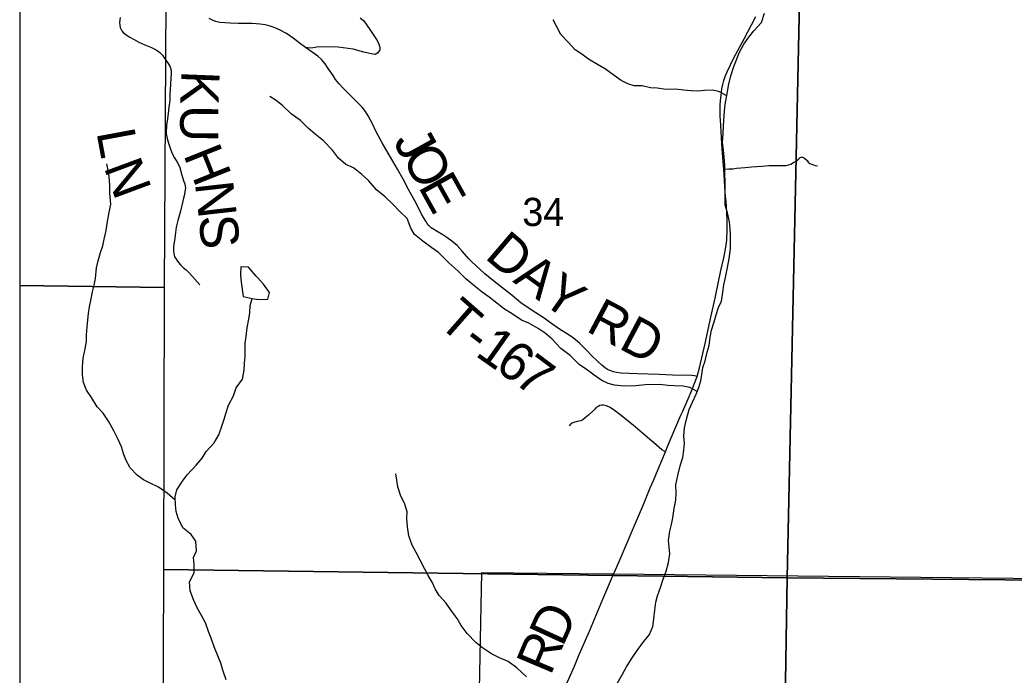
# Model space of a CAD drawing. Extents: x 0 to 191, y 0 to 55.
# Drawn here: x 184.17 to 185.647, y 51.316 to 52.289 of the extents above; entities that cross this region are included whole.
import ezdxf

# ---------------------------------------------------------------- set-up
doc = ezdxf.new("R2010")
doc.units = 0
for name, color, linetype in [('GM_X_Corporation', 7, 'Continuous'), ('GM_X_County_Road', 7, 'Continuous'), ('GM_X_County_Road_Text', 7, 'Continuous'), ('GM_X_Minor_Lake', 7, 'Continuous'), ('GM_X_Minor_River', 7, 'Continuous'), ('GM_X_Section_Text', 7, 'Continuous'), ('GM_X_Township_Road', 7, 'Continuous'), ('GM_X_Township_Road_Text', 7, 'Continuous')]:
    doc.layers.add(name, color=color, linetype=linetype)

msp = doc.modelspace()

# ---------------------------------------------------------------- linework, layer by layer
at = {"layer": 'GM_X_Corporation'}
for points in [[(187.8766, 54.1257), (187.4205, 54.1315), (187.3845, 54.1319), (186.7662, 54.1447), (186.7401, 54.1422), (185.9791, 54.1551), (185.8681, 54.1568), (185.8476, 54.1564), (184.4129, 54.1665), (184.4114, 53.9192), (184.1701, 53.923), (184.1701, 47.9197)], [(184.8319, 50.3472), (184.8438, 50.7018), (184.8438, 50.7041), (184.8504, 51.1664), (184.8504, 51.1691), (184.8564, 51.468), (185.0493, 51.466), (185.0519, 51.466), (185.737, 51.4587), (185.8223, 51.4579), (185.8471, 52.9493), (185.8472, 52.953), (185.8634, 53.9305), (185.8653, 54.0182), (185.8655, 54.0321), (185.8681, 54.1568), (185.8476, 54.1564), (184.4129, 54.1665), (184.4114, 53.9192), (184.1701, 53.923), (184.1701, 49.9388)], [(184.8319, 50.3472), (184.8438, 50.7018), (184.8438, 50.7041), (184.8504, 51.1664), (184.8504, 51.1691), (184.8564, 51.468), (185.0493, 51.466), (185.0519, 51.466), (185.737, 51.4587), (185.8223, 51.4579), (185.8471, 52.9493), (185.8472, 52.953), (185.8634, 53.9305), (185.8653, 54.0182), (185.8655, 54.0321), (185.8681, 54.1568), (185.9791, 54.1551), (186.7401, 54.1422), (186.7662, 54.1447), (187.3845, 54.1319), (187.4205, 54.1315), (187.8766, 54.1257)]]:
    msp.add_lwpolyline(points, dxfattribs=at)
for points in [[(184.1701, 52.9098), (184.1701, 51.8943), (184.385, 51.8913), (184.3885, 52.4898), (184.3932, 52.9078)], [(184.3885, 52.4898), (185.3319, 52.4794), (185.31, 51.4601), (184.3837, 51.4722), (184.385, 51.8913)], [(185.3319, 52.4794), (186.3443, 52.462), (186.336, 51.4505), (185.31, 51.4601)], [(184.1701, 51.8943), (184.1701, 50.9485), (184.3819, 50.9465), (184.3837, 51.4722), (184.385, 51.8913)], [(185.31, 51.4601), (185.2935, 50.4401), (184.3778, 50.4493), (184.3819, 50.9465), (184.3837, 51.4722)], [(186.336, 51.4505), (186.3245, 50.4222), (185.2935, 50.4401), (185.31, 51.4601)]]:
    msp.add_lwpolyline(points, close=True, dxfattribs=at)
at = {"layer": 'GM_X_County_Road'}
for points in [[(185.0533, 51.4683), (185.0619, 51.488), (185.0816, 51.5344), (185.0963, 51.5691), (185.1064, 51.5937), (185.1112, 51.6045), (185.1185, 51.6216), (185.129, 51.6472), (185.1323, 51.6551), (185.1447, 51.6844), (185.1522, 51.7018), (185.1549, 51.7079), (185.163, 51.726), (185.1684, 51.7388), (185.1763, 51.7592), (185.1799, 51.7719), (185.1882, 51.8084), (185.1967, 51.8476), (185.2028, 51.8756), (185.2039, 51.8805), (185.2116, 51.9165), (185.216, 51.9356), (185.2182, 51.9485), (185.2201, 51.9616), (185.221, 51.9779), (185.2207, 51.9917), (185.2197, 52.0133), (185.2179, 52.0329), (185.2158, 52.0673), (185.2148, 52.0783), (185.2127, 52.1048), (185.2112, 52.1328), (185.2105, 52.1467), (185.2106, 52.1619), (185.211, 52.1692), (185.2118, 52.1768), (185.2129, 52.1864), (185.2145, 52.193), (185.2161, 52.1991), (185.2181, 52.2048), (185.2206, 52.2118), (185.2305, 52.2329), (185.2459, 52.261), (185.257, 52.2817), (185.2634, 52.2941)], [(184.8059, 51.1216), (184.8253, 51.1406), (184.8506, 51.1659), (184.8828, 51.1979), (184.9242, 51.2399), (184.9415, 51.2574), (184.963, 51.2794), (184.9676, 51.284), (184.9804, 51.2997), (184.984, 51.3063), (184.9939, 51.3288), (185.0011, 51.3463), (185.0161, 51.381), (185.0362, 51.4285), (185.0521, 51.4654), (185.0533, 51.4683)]]:
    msp.add_lwpolyline(points, dxfattribs=at)
at = {"layer": 'GM_X_Minor_Lake'}
for points in [[(184.5238, 51.9056), (184.5213, 51.9084), (184.5099, 51.9216), (184.4985, 51.9224), (184.4978, 51.9098), (184.4989, 51.8996), (184.502, 51.8783)], [(184.502, 51.8783), (184.5149, 51.8753), (184.5248, 51.8735), (184.5385, 51.8739), (184.5407, 51.8838), (184.532, 51.8963), (184.5238, 51.9056)]]:
    msp.add_lwpolyline(points, dxfattribs=at)
at = {"layer": 'GM_X_Minor_River'}
for points in [[(185.2201, 52.176), (185.2086, 52.1826), (185.1987, 52.1845), (185.1873, 52.1844), (185.1775, 52.1832), (185.1672, 52.1836), (185.1566, 52.1847), (185.1441, 52.1862), (185.13, 52.1857), (185.1167, 52.1876), (185.1069, 52.1883), (185.0947, 52.1909), (185.0826, 52.1913), (185.0731, 52.1939), (185.0632, 52.1992), (185.053, 52.2064), (185.04, 52.2158), (185.0283, 52.2226), (185.0146, 52.2309), (185.0051, 52.2381), (184.9952, 52.2445), (184.9849, 52.2555), (184.9735, 52.2676), (184.9674, 52.2798), (184.9621, 52.2892)], [(185.1977, 51.8279), (185.2014, 51.8404), (185.2044, 51.851), (185.2078, 51.8617), (185.2124, 51.8712), (185.2146, 51.8845), (185.2161, 51.8955), (185.2183, 51.9065), (185.2213, 51.9213), (185.224, 51.9343), (185.2258, 51.9491), (185.2258, 51.9696), (185.2254, 51.9791), (185.2242, 51.989), (185.2212, 52.0022), (185.2181, 52.0136), (185.218, 52.0375), (185.218, 52.0474), (185.2176, 52.0611), (185.2172, 52.0725), (185.2164, 52.0854), (185.2152, 52.0956), (185.2141, 52.107), (185.2148, 52.1203), (185.2152, 52.1306), (185.2159, 52.1401), (185.217, 52.1534), (185.2181, 52.1633), (185.2211, 52.1823), (185.223, 52.1918), (185.2264, 52.2062), (185.2305, 52.2199), (185.2346, 52.2298), (185.2388, 52.24), (185.2456, 52.253), (185.2528, 52.2633), (185.2603, 52.2728), (185.2717, 52.2853), (185.2762, 52.299)], [(185.1763, 51.7371), (185.1652, 51.7431), (185.1557, 51.7449), (185.1425, 51.7453), (185.133, 51.7456), (185.1201, 51.7471), (185.0988, 51.747), (185.0852, 51.7455), (185.0677, 51.745), (185.0537, 51.7461), (185.0442, 51.7487), (185.0347, 51.7533), (185.0233, 51.7612), (185.0134, 51.7684), (185.0009, 51.7771), (184.9875, 51.7903), (184.9739, 51.8009), (184.9609, 51.8145), (184.9503, 51.8236), (184.94, 51.8304), (184.926, 51.8387), (184.9153, 51.8429), (184.9028, 51.8512), (184.8887, 51.8602), (184.8785, 51.8682), (184.8674, 51.8772), (184.8568, 51.8844), (184.8469, 51.8924), (184.8325, 51.9041), (184.8207, 51.9162), (184.8074, 51.9283), (184.7918, 51.9435), (184.7819, 51.9506), (184.7686, 51.9601), (184.7564, 51.9703), (184.7511, 51.9798), (184.7454, 51.9938), (184.734, 52.0048), (184.7248, 52.015), (184.7127, 52.0264), (184.6997, 52.0366), (184.6879, 52.0502), (184.678, 52.0593), (184.6659, 52.0695), (184.6545, 52.074), (184.6435, 52.0835), (184.6347, 52.0956), (184.621, 52.1092), (184.6085, 52.1191), (184.5982, 52.1281), (184.5868, 52.1395), (184.5731, 52.1497), (184.5602, 52.1618), (184.5507, 52.1694), (184.5412, 52.1754)], [(184.4008, 51.5754), (184.3889, 51.586), (184.376, 51.595), (184.3634, 51.6007), (184.3539, 51.6056), (184.3444, 51.6124), (184.3341, 51.6234), (184.3277, 51.6355), (184.3242, 51.645), (184.3212, 51.6548), (184.3162, 51.6655), (184.3097, 51.6783), (184.3017, 51.6927), (184.2937, 51.7045), (184.285, 51.7143), (184.2766, 51.728), (184.269, 51.739), (184.2644, 51.7503), (184.2633, 51.7617), (184.2632, 51.7735), (184.2643, 51.7864), (184.267, 51.8005), (184.2688, 51.8111), (184.2692, 51.821), (184.2699, 51.8331), (184.271, 51.8434), (184.2721, 51.8529), (184.2736, 51.8628), (184.2759, 51.8745), (184.2781, 51.8848), (184.2804, 51.8951), (184.2823, 51.9049), (184.2838, 51.9209), (184.2864, 51.9311), (184.2898, 51.9433), (184.2935, 51.9532), (184.2954, 51.9635), (184.298, 51.976), (184.2995, 51.9866), (184.3022, 52.0003), (184.3052, 52.0155), (184.3036, 52.0315), (184.3036, 52.044), (184.3028, 52.0558), (184.3012, 52.0652), (184.2993, 52.0751)], [(184.4764, 51.3087), (184.4718, 51.3231), (184.4688, 51.3334), (184.4642, 51.344), (184.4588, 51.3573), (184.4542, 51.3705), (184.4504, 51.3804), (184.4459, 51.3933), (184.4398, 51.4039), (184.4333, 51.4153), (184.4287, 51.4266), (184.423, 51.4407), (184.4222, 51.4543), (184.429, 51.4676), (184.429, 51.4802), (184.4278, 51.4904), (184.4323, 51.5003), (184.4315, 51.5143), (184.4243, 51.5242), (184.4121, 51.5344), (184.4053, 51.5488), (184.4022, 51.5587), (184.4011, 51.5685), (184.4007, 51.5803), (184.4033, 51.5906), (184.4116, 51.6035), (184.4184, 51.613), (184.432, 51.6275), (184.4407, 51.6381), (184.4468, 51.648), (184.4585, 51.6606), (184.4657, 51.6724), (184.4702, 51.6853), (184.4736, 51.696), (184.4763, 51.7058), (184.48, 51.7165), (184.4872, 51.7306), (184.4913, 51.7423), (184.5008, 51.7553), (184.5034, 51.7686), (184.5038, 51.7788), (184.5045, 51.7891), (184.5045, 51.7993), (184.5049, 51.8088), (184.506, 51.8187), (184.5078, 51.8313), (184.5101, 51.8445), (184.5116, 51.854), (184.5123, 51.8647), (184.5149, 51.8753)], [(185.0573, 51.303), (185.0653, 51.3167), (185.0713, 51.3278), (185.0796, 51.3411), (185.0861, 51.3506), (185.0951, 51.3628), (185.1054, 51.3761), (185.1106, 51.3875), (185.1118, 51.3989), (185.1133, 51.4118), (185.1151, 51.424), (185.1174, 51.4335), (185.1223, 51.4471), (185.1253, 51.4566), (185.1302, 51.4699), (185.1336, 51.4829), (185.1358, 51.4958), (185.1335, 51.5155), (185.1357, 51.5292), (185.138, 51.5391), (185.1399, 51.5493), (185.1421, 51.563), (185.1447, 51.5755), (185.1451, 51.5866), (185.1447, 51.5983), (185.1477, 51.612), (185.1511, 51.6264), (185.1552, 51.639), (185.1567, 51.6496), (185.1575, 51.6595), (185.1567, 51.6705), (185.1574, 51.683), (185.1604, 51.6956), (185.1645, 51.7104), (185.1695, 51.7211), (185.1747, 51.7332), (185.1785, 51.7427), (185.1815, 51.7526), (185.183, 51.7621), (185.1845, 51.7724), (185.1883, 51.7826), (185.1913, 51.7956), (185.1939, 51.8054), (185.1958, 51.8176), (185.1977, 51.8279)], [(184.9226, 51.3132), (184.9085, 51.3261), (184.8956, 51.3355), (184.8827, 51.3412), (184.8709, 51.3472), (184.8573, 51.3559), (184.8474, 51.3642), (184.8348, 51.3775), (184.8257, 51.3892), (184.8196, 51.3994), (184.8108, 51.4116), (184.8032, 51.4222), (184.7929, 51.4339), (184.7869, 51.4437), (184.7827, 51.4536), (184.7766, 51.4635), (184.7716, 51.4729), (184.7648, 51.4862), (184.759, 51.4979), (184.7529, 51.5086), (184.748, 51.5226), (184.746, 51.5359), (184.7449, 51.5484), (184.7452, 51.5583), (184.7418, 51.5696), (184.7353, 51.5829), (184.7315, 51.5951), (184.7299, 51.6053), (184.7288, 51.6148)]]:
    msp.add_lwpolyline(points, dxfattribs=at)
at = {"layer": 'GM_X_Township_Road'}
for points in [[(184.3189, 52.2928), (184.3181, 52.2853), (184.3185, 52.2811), (184.3191, 52.278), (184.3201, 52.2759), (184.3217, 52.273), (184.3237, 52.2705), (184.3274, 52.2673), (184.3322, 52.264), (184.3397, 52.2597), (184.347, 52.2561), (184.3557, 52.2522), (184.3658, 52.2481), (184.3726, 52.2445), (184.3779, 52.2407), (184.3818, 52.2367), (184.3844, 52.2326), (184.3896, 52.2256), (184.3929, 52.2205), (184.394, 52.2173), (184.3948, 52.2139), (184.3949, 52.2082), (184.3945, 52.2028), (184.3937, 52.1931), (184.393, 52.1788), (184.3926, 52.1692), (184.3914, 52.1596), (184.3903, 52.1501), (184.3887, 52.1384), (184.3878, 52.1331), (184.3874, 52.1205), (184.3887, 52.1128), (184.3908, 52.1058), (184.394, 52.0969), (184.3964, 52.0908), (184.3997, 52.0839), (184.4036, 52.0777), (184.4061, 52.0734), (184.4076, 52.0699), (184.4108, 52.0582), (184.4138, 52.0489), (184.4151, 52.0454), (184.4158, 52.0422), (184.4161, 52.0394), (184.4153, 52.0343), (184.4144, 52.0298), (184.4132, 52.0243), (184.4123, 52.0199), (184.4085, 52.0049), (184.4049, 51.9909), (184.4022, 51.9809), (184.4011, 51.9734), (184.4001, 51.9647), (184.3991, 51.9582), (184.3984, 51.953), (184.3981, 51.9489), (184.3984, 51.9452), (184.3992, 51.9397), (184.4, 51.937), (184.4016, 51.9344), (184.403, 51.932), (184.4055, 51.9288), (184.4086, 51.9252), (184.4128, 51.9214), (184.4171, 51.9177), (184.4222, 51.9127), (184.4302, 51.9039), (184.4375, 51.8955)], [(185.1763, 51.7592), (185.1722, 51.7601), (185.1682, 51.7605), (185.1395, 51.7613), (185.12, 51.7621), (185.0877, 51.7634), (185.063, 51.7644), (185.0566, 51.7652), (185.052, 51.7662), (185.0465, 51.7681), (185.0432, 51.7697), (185.0402, 51.7714), (185.0344, 51.7762), (185.0289, 51.7813), (185.0192, 51.7905), (185.0128, 51.7974), (185.0018, 51.8083), (184.9922, 51.8165), (184.9822, 51.8231), (184.9717, 51.8295), (184.9617, 51.8364), (184.9473, 51.8469), (184.9312, 51.8572), (184.9142, 51.8689), (184.9013, 51.8794), (184.8716, 51.903), (184.8608, 51.912), (184.8473, 51.924), (184.8414, 51.9294), (184.8372, 51.9341), (184.8271, 51.9454), (184.8195, 51.9537), (184.8116, 51.9603), (184.8042, 51.9659), (184.7982, 51.9699), (184.7899, 51.9748), (184.7834, 51.9785), (184.7812, 51.98), (184.7795, 51.9816), (184.7774, 51.9836), (184.7752, 51.9863), (184.773, 51.9899), (184.7672, 51.9993), (184.7594, 52.0156), (184.7473, 52.0373), (184.7393, 52.0525), (184.7312, 52.0671), (184.7174, 52.0912), (184.7081, 52.1063), (184.6991, 52.1237), (184.6944, 52.1338), (184.6875, 52.1463), (184.6834, 52.1529), (184.6786, 52.1596), (184.6502, 52.1876), (184.644, 52.1944), (184.6391, 52.2006), (184.6356, 52.2063), (184.6283, 52.2167), (184.6234, 52.2237), (184.618, 52.2304), (184.6127, 52.2353), (184.5945, 52.2481), (184.5849, 52.2552), (184.5762, 52.2617), (184.5661, 52.2687), (184.5557, 52.2745), (184.5502, 52.277), (184.5451, 52.2789), (184.5405, 52.2802), (184.5347, 52.2816), (184.5268, 52.2826), (184.5152, 52.2836), (184.5064, 52.2839), (184.4942, 52.2836), (184.4819, 52.284), (184.4669, 52.2851), (184.4614, 52.2869), (184.4574, 52.2884), (184.4515, 52.2911)], [(184.6757, 52.2919), (184.6812, 52.2875), (184.69, 52.275), (184.7011, 52.2584), (184.7035, 52.2531), (184.7049, 52.2485), (184.7046, 52.2446), (184.702, 52.2402), (184.698, 52.2378), (184.692, 52.2385), (184.6812, 52.241), (184.6653, 52.2456), (184.6429, 52.2487), (184.6249, 52.2492), (184.6111, 52.2486), (184.6056, 52.2477), (184.6011, 52.2472), (184.598, 52.2474), (184.5945, 52.2481)], [(185.2158, 52.0673), (185.2235, 52.0677), (185.2293, 52.068), (185.2349, 52.0686), (185.2475, 52.0696), (185.2572, 52.0705), (185.265, 52.071), (185.2726, 52.0719), (185.2828, 52.0726), (185.2957, 52.0727), (185.3038, 52.0725), (185.3085, 52.0726), (185.3119, 52.0735), (185.3152, 52.0748), (185.3195, 52.077), (185.3238, 52.0797), (185.3271, 52.0825), (185.3292, 52.0845), (185.331, 52.0851), (185.3329, 52.085), (185.3355, 52.0837), (185.3395, 52.08), (185.3414, 52.0778), (185.3437, 52.0758), (185.3459, 52.0747), (185.3491, 52.0737), (185.3518, 52.0729), (185.3552, 52.0721)], [(185.129, 51.6472), (185.1239, 51.6504), (185.1114, 51.6613), (185.1025, 51.6688), (185.0951, 51.6752), (185.0812, 51.6868), (185.0717, 51.6941), (185.0634, 51.7011), (185.0535, 51.7087), (185.0468, 51.7132), (185.0414, 51.7156), (185.0373, 51.7166), (185.0347, 51.7168), (185.0319, 51.7162), (185.029, 51.7148), (185.0264, 51.7129), (185.0246, 51.7112), (185.0229, 51.7092), (185.015, 51.7019), (185.01, 51.6979), (185.0066, 51.6948), (185.0036, 51.6931), (184.9981, 51.6924), (184.9929, 51.6911), (184.9892, 51.6893), (184.9861, 51.6859)]]:
    msp.add_lwpolyline(points, dxfattribs=at)

# ---------------------------------------------------------------- texts
at = {"layer": 'GM_X_County_Road_Text'}
for s, rotation, p in [('D', 65.5141, (184.9763, 51.3562)), ('R', 67.1781, (184.9583, 51.3136))]:
    msp.add_text(s, height=0.0568, rotation=rotation, dxfattribs=at).set_placement(p)
at = {"layer": 'GM_X_Section_Text'}
msp.add_text('34', height=0.04186, rotation=0, dxfattribs=at).set_placement((184.9165, 51.9828))
at = {"layer": 'GM_X_Township_Road_Text'}
for s, height, rotation, p in [('K', 0.0568, 267.7044, (184.4103, 52.2146)), ('U', 0.0568, 269.6189, (184.4083, 52.1626)), ('L', 0.0568, 280.5115, (184.2837, 52.1222)), ('J', 0.0568, 299.046, (184.7237, 52.1084)), ('H', 0.0568, 291.8381, (184.4124, 52.0891)), ('O', 0.0568, 299.0501, (184.7366, 52.0851)), ('N', 0.0568, 290.3404, (184.2943, 52.0703)), ('E', 0.0568, 299.1277, (184.761, 52.0413)), ('N', 0.0568, 276.4396, (184.43, 52.0466)), ('S', 0.0568, 275.5825, (184.4356, 51.9971)), ('D', 0.0568, 319.4659, (184.8592, 51.9359)), ('A', 0.0568, 324.1196, (184.9011, 51.9003)), ('Y', 0.0568, 324.5822, (184.942, 51.8707)), ('T', 0.0568, 318.727, (184.7892, 51.8373)), ('RD', 0.05682, 332.1043, (185.0095, 51.8275)), ('-', 0.0568, 323.0085, (184.8247, 51.8064)), ('1', 0.0568, 324.7373, (184.8449, 51.7912)), ('6', 0.0568, 324.9271, (184.8736, 51.7709)), ('7', 0.0568, 323.2789, (184.9019, 51.751))]:
    msp.add_text(s, height=height, rotation=rotation, dxfattribs=at).set_placement(p)

doc.saveas('drawing.dxf')
